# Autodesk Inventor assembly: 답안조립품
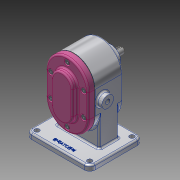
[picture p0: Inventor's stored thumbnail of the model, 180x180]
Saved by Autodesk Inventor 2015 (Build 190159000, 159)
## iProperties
Created: 2020-09
Part Number: 답안조립품
Document SubType Name: Assembly
Designer: LINEART-SSD.D4.16.05
Author: LINEART-SSD.D4.16.05
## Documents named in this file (11)
- C:\Users\LINEART-SSD.D4.16.05\Desktop\700906V1023\답안조립품.iam
- C:\Users\LINEART-SSD.D4.16.05\Desktop\700906V1023\본체.ipt
- C:\Users\LINEART-SSD.D4.16.05\Desktop\700906V1023\커버.ipt
- C:\Users\LINEART-SSD.D4.16.05\Desktop\700906V1023\베어링부시.ipt
- C:\Users\LINEART-SSD.D4.16.05\Desktop\700906V1023\메인축.ipt
- C:\Users\LINEART-SSD.D4.16.05\Desktop\700906V1023\서브축.ipt
- C:\Users\LINEART-SSD.D4.16.05\Desktop\700906V1023\개스킷.ipt
- C:\Users\LINEART-SSD.D4.16.05\Desktop\700906V1023\키 6 x 6 x 18.ipt
- C:\Users\LINEART-SSD.D4.16.05\Desktop\700906V1023\스퍼기어.ipt
- C:\Users\LINEART-SSD.D4.16.05\Desktop\700906V1023\오일 실 16 28 7.ipt
- C:\Users\LINEART-SSD.D4.16.05\Desktop\700906V1023\볼트 M5.ipt
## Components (1 placed, 1 different names)
1. 개스킷:1
